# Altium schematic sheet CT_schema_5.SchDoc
size 255 x 245 mm
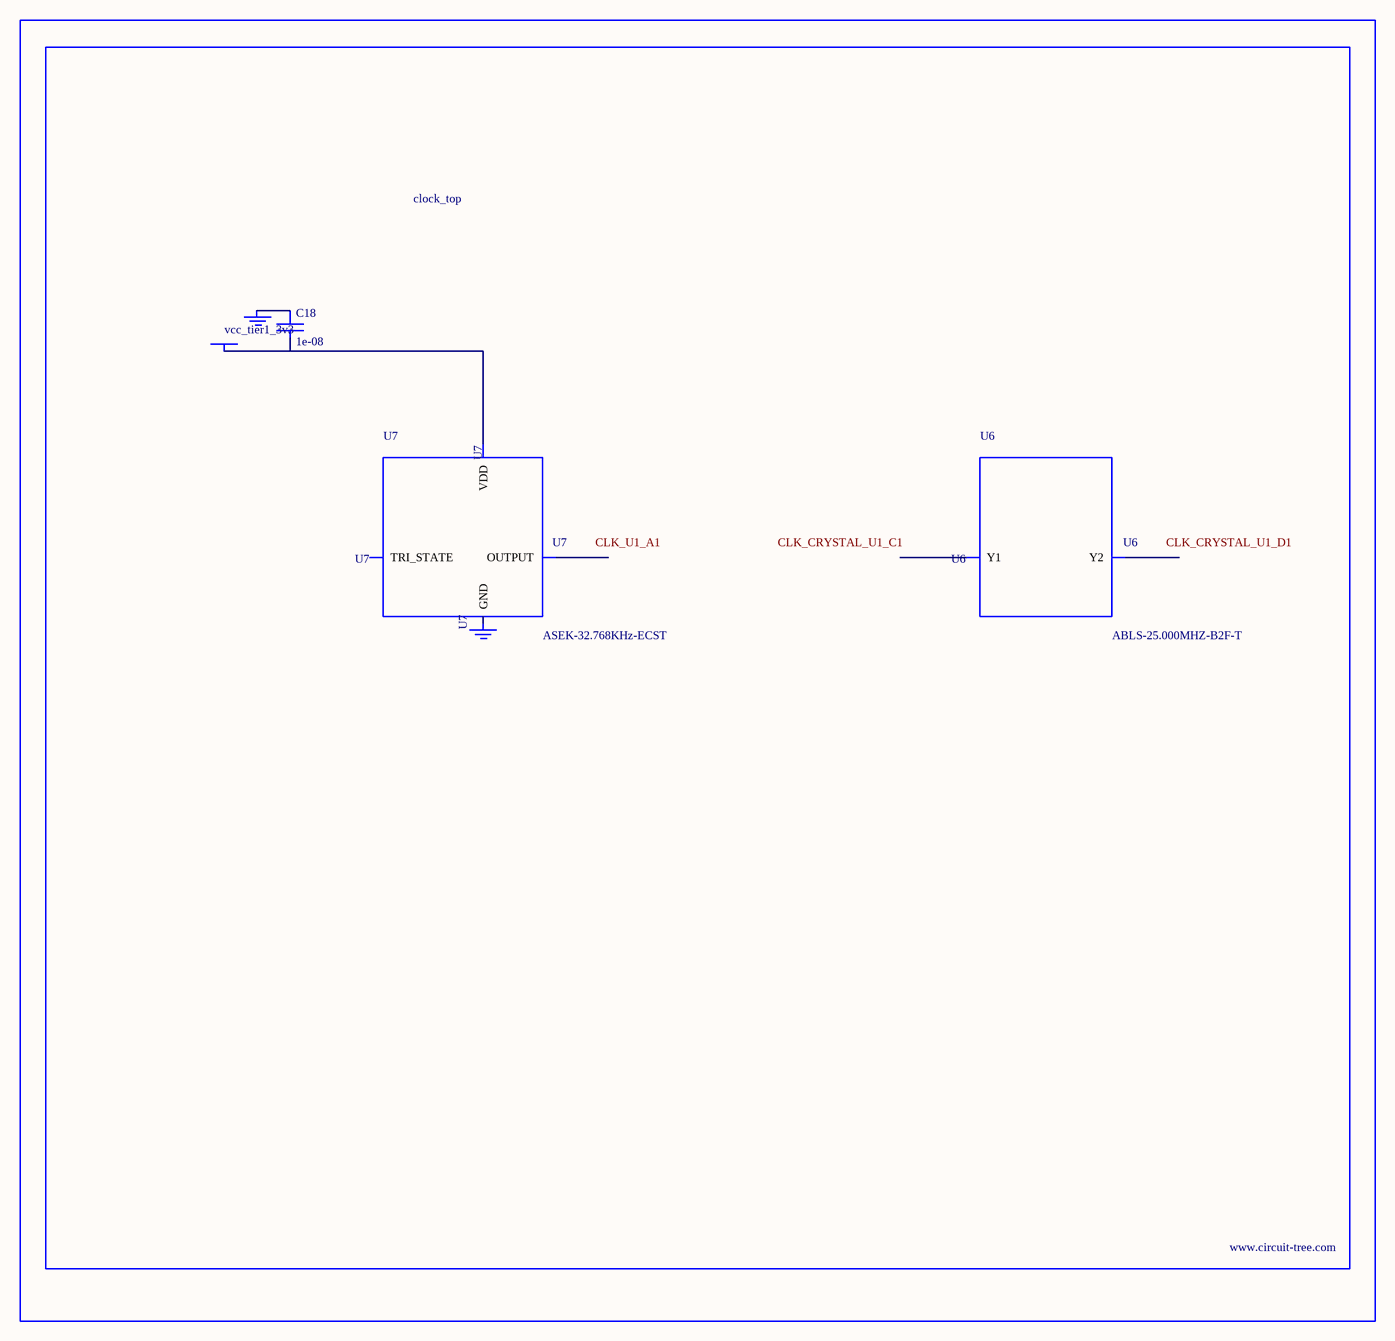
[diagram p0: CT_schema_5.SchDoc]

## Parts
BORDER4  (no value)
C18  1e-08  [C0402]
GND_INSTANCE_4_0  (no value)
GND_INSTANCE_4_1  (no value)
POWER_INSTANCE_4_0  vcc_tier1_3v3
U6  ABLS-25.000MHZ-B2F-T  [ABLS-25.000MHZ-B2F-T]
U7  ASEK-32.768KHz-ECST  [ASEK]

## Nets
NetC18_1: C18.1 GND_INSTANCE_4_0.0(GND)
NetC18_2: C18.2 POWER_INSTANCE_4_0.0(PWR) U7.4(VDD)

Not connected (* = marked no-connect by the designer): GND_INSTANCE_4_1 0(GND); U6 1(Y1) 2(Y2); U7 1(TRI_STATE) 2(GND) 3(OUTPUT)

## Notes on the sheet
- Labels drawn without touching a wire or pin: CLK_CRYSTAL_U1_C1, CLK_CRYSTAL_U1_D1, CLK_U1_A1

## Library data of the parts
BORDER4 = BORDER_PAGE4
C18 = C0402C103K3RAC
GND_INSTANCE_4_0 GND_INSTANCE_4_1 = GND
POWER_INSTANCE_4_0 = PWR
